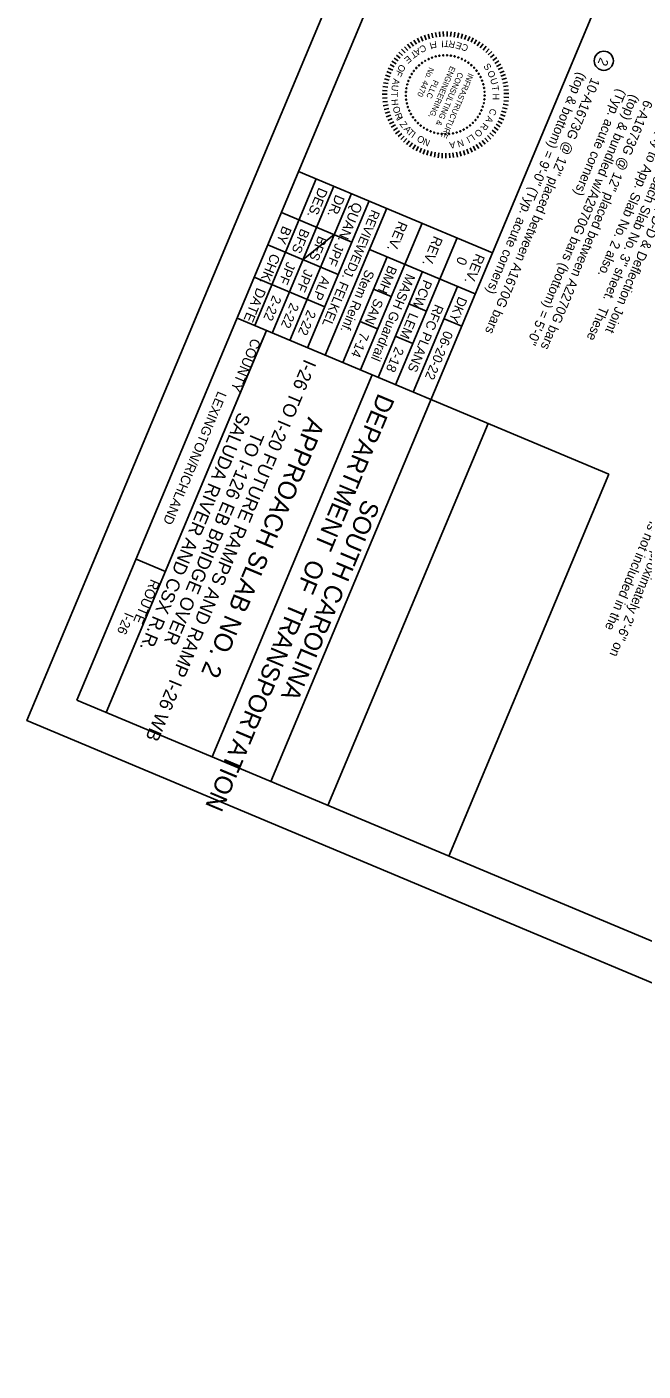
# Model space of a CAD drawing. Extents: x 1968564 to 1968701, y 796599 to 796766.
# Drawn here: x 1968563.8 to 1968596.1, y 796598.9 to 796669.3 of the extents above; entities that cross this region are included whole.
import ezdxf

# ---------------------------------------------------------------- set-up
doc = ezdxf.new("R2010")
doc.units = 0
for name, color, linetype in [('BR_AUTO DIMENSION', 7, 'Continuous'), ('BR_BORDER LINES', 7, 'Continuous'), ('BR_TEXT', 7, 'Continuous'), ('Level 31', 7, 'Continuous')]:
    doc.layers.add(name, color=color, linetype=linetype)

msp = doc.modelspace()

# ---------------------------------------------------------------- linework, layer by layer
at = {"layer": 'BR_AUTO DIMENSION'}
msp.add_circle((1968594.037, 796667.481), 0.502, dxfattribs=at)
at = {"layer": 'BR_BORDER LINES'}
for p, q in [((1968618.549, 796758.212), (1968566.464, 796634.028)), ((1968596.513, 796677.23), (1968588.212, 796657.44)), ((1968578.99, 796661.308), (1968575.767, 796653.623)), ((1968578.068, 796661.695), (1968588.212, 796657.44)), ((1968579.912, 796660.921), (1968576.689, 796653.236)), ((1968580.835, 796660.534), (1968577.611, 796652.849)), ((1968581.757, 796660.147), (1968578.534, 796652.462)), ((1968582.679, 796659.761), (1968579.456, 796652.076)), ((1968580.854, 796657.996), (1968577.166, 796659.543)), ((1968584.524, 796658.987), (1968581.3, 796651.302)), ((1968580.145, 796656.305), (1968576.456, 796657.852)), ((1968587.31, 796655.288), (1968581.777, 796657.609)), ((1968586.368, 796658.213), (1968583.145, 796650.528)), ((1968588.212, 796657.44), (1968576.609, 796629.774)), ((1968582.699, 796657.222), (1968580.378, 796651.689)), ((1968579.436, 796654.614), (1968575.747, 796656.161)), ((1968584.543, 796656.448), (1968582.222, 796650.915)), ((1968581.99, 796655.531), (1968582.912, 796655.145)), ((1968586.388, 796655.675), (1968584.067, 796650.142)), ((1968583.834, 796654.758), (1968584.756, 796654.371)), ((1968576.382, 796653.365), (1968568.001, 796633.384)), ((1968574.845, 796654.01), (1968594.308, 796645.846)), ((1968581.281, 796653.841), (1968582.203, 796653.454)), ((1968585.679, 796653.984), (1968586.601, 796653.597)), ((1968576.231, 796653.005), (1968568.001, 796633.384)), ((1968583.125, 796653.067), (1968584.047, 796652.68)), ((1968581.915, 796651.044), (1968573.534, 796631.062)), ((1968581.915, 796651.044), (1968581.915, 796651.044)), ((1968587.983, 796648.498), (1968579.603, 796628.518)), ((1968594.308, 796645.846), (1968585.928, 796625.865)), ((1968569.559, 796641.406), (1968571.096, 796640.761)), ((1968566.464, 796634.028), (1968643.927, 796601.539))]:
    msp.add_line(p, q, dxfattribs=at)
at = {"layer": 'BR_TEXT'}
for p, q in [((1968584.652, 796668.818), (1968584.737, 796668.578)), ((1968584.844, 796668.88), (1968584.915, 796668.635)), ((1968585.04, 796668.93), (1968585.095, 796668.681)), ((1968585.238, 796668.967), (1968585.278, 796668.716)), ((1968585.438, 796668.993), (1968585.463, 796668.74)), ((1968585.64, 796669.006), (1968585.649, 796668.752)), ((1968585.842, 796669.007), (1968585.836, 796668.753)), ((1968586.043, 796668.996), (1968586.022, 796668.742)), ((1968586.244, 796668.973), (1968586.207, 796668.721)), ((1968586.443, 796668.937), (1968586.39, 796668.688)), ((1968586.639, 796668.889), (1968586.571, 796668.643)), ((1968586.832, 796668.829), (1968586.749, 796668.588)), ((1968583.608, 796668.216), (1968583.774, 796668.022)), ((1968583.766, 796668.342), (1968583.919, 796668.139)), ((1968583.93, 796668.458), (1968584.071, 796668.246)), ((1968584.102, 796668.565), (1968584.23, 796668.344)), ((1968584.28, 796668.66), (1968584.394, 796668.433)), ((1968584.463, 796668.745), (1968584.563, 796668.511)), ((1968587.021, 796668.758), (1968586.924, 796668.523)), ((1968587.205, 796668.675), (1968587.094, 796668.446)), ((1968587.384, 796668.582), (1968587.259, 796668.36)), ((1968587.557, 796668.477), (1968587.418, 796668.263)), ((1968587.723, 796668.362), (1968587.572, 796668.157)), ((1968587.881, 796668.238), (1968587.718, 796668.042)), ((1968588.032, 796668.103), (1968587.858, 796667.918)), ((1968582.951, 796667.454), (1968583.167, 796667.319)), ((1968583.063, 796667.622), (1968583.271, 796667.474)), ((1968583.186, 796667.782), (1968583.384, 796667.622)), ((1968583.318, 796667.935), (1968583.506, 796667.763)), ((1968583.459, 796668.08), (1968583.636, 796667.897)), ((1968588.175, 796667.96), (1968587.989, 796667.786)), ((1968588.308, 796667.809), (1968588.112, 796667.646)), ((1968588.432, 796667.649), (1968588.227, 796667.499)), ((1968588.546, 796667.483), (1968588.332, 796667.345)), ((1968582.61, 796666.724), (1968582.852, 796666.645)), ((1968582.678, 796666.914), (1968582.915, 796666.82)), ((1968582.758, 796667.099), (1968582.989, 796666.992)), ((1968582.849, 796667.279), (1968583.073, 796667.158)), ((1968588.65, 796667.309), (1968588.428, 796667.185)), ((1968588.743, 796667.13), (1968588.513, 796667.02)), ((1968588.825, 796666.945), (1968588.589, 796666.849)), ((1968588.895, 796666.756), (1968588.654, 796666.674)), ((1968582.476, 796666.134), (1968582.728, 796666.1)), ((1968582.509, 796666.333), (1968582.759, 796666.284)), ((1968582.553, 796666.53), (1968582.8, 796666.466)), ((1968588.954, 796666.563), (1968588.708, 796666.496)), ((1968589, 796666.366), (1968588.751, 796666.315)), ((1968589.035, 796666.167), (1968588.783, 796666.131)), ((1968582.447, 796665.731), (1968582.702, 796665.729)), ((1968582.451, 796665.529), (1968582.706, 796665.542)), ((1968582.455, 796665.933), (1968582.709, 796665.915)), ((1968582.468, 796665.328), (1968582.721, 796665.357)), ((1968589.052, 796665.362), (1968588.798, 796665.387)), ((1968589.058, 796665.967), (1968588.804, 796665.946)), ((1968589.066, 796665.563), (1968588.811, 796665.573)), ((1968589.068, 796665.765), (1968588.813, 796665.76)), ((1968582.496, 796665.128), (1968582.747, 796665.172)), ((1968582.537, 796664.93), (1968582.785, 796664.99)), ((1968582.59, 796664.735), (1968582.834, 796664.81)), ((1968582.654, 796664.544), (1968582.893, 796664.633)), ((1968588.873, 796664.576), (1968588.633, 796664.662)), ((1968588.935, 796664.768), (1968588.691, 796664.839)), ((1968588.986, 796664.963), (1968588.738, 796665.02)), ((1968589.025, 796665.162), (1968588.774, 796665.203)), ((1968582.731, 796664.357), (1968582.963, 796664.46)), ((1968582.818, 796664.175), (1968583.044, 796664.292)), ((1968582.916, 796663.998), (1968583.135, 796664.129)), ((1968583.025, 796663.828), (1968583.235, 796663.972)), ((1968588.51, 796663.857), (1968588.298, 796663.998)), ((1968588.617, 796664.028), (1968588.397, 796664.156)), ((1968588.713, 796664.205), (1968588.486, 796664.32)), ((1968588.799, 796664.388), (1968588.565, 796664.489)), ((1968583.144, 796663.665), (1968583.345, 796663.822)), ((1968583.273, 796663.51), (1968583.464, 796663.678)), ((1968583.411, 796663.362), (1968583.591, 796663.542)), ((1968583.558, 796663.224), (1968583.727, 796663.414)), ((1968583.713, 796663.094), (1968583.87, 796663.295)), ((1968583.875, 796662.974), (1968584.02, 796663.184)), ((1968587.668, 796662.994), (1968587.521, 796663.202)), ((1968587.83, 796663.115), (1968587.67, 796663.314)), ((1968587.983, 796663.246), (1968587.812, 796663.435)), ((1968588.129, 796663.387), (1968587.946, 796663.564)), ((1968588.265, 796663.535), (1968588.072, 796663.702)), ((1968588.392, 796663.692), (1968588.189, 796663.846)), ((1968584.045, 796662.864), (1968584.176, 796663.083)), ((1968584.221, 796662.765), (1968584.339, 796662.991)), ((1968584.402, 796662.677), (1968584.506, 796662.91)), ((1968584.589, 796662.6), (1968584.678, 796662.838)), ((1968584.78, 796662.535), (1968584.855, 796662.778)), ((1968584.974, 796662.481), (1968585.034, 796662.728)), ((1968585.172, 796662.439), (1968585.217, 796662.69)), ((1968585.372, 796662.409), (1968585.401, 796662.662)), ((1968585.573, 796662.392), (1968585.587, 796662.646)), ((1968585.775, 796662.387), (1968585.773, 796662.641)), ((1968585.977, 796662.394), (1968585.96, 796662.648)), ((1968586.178, 796662.414), (1968586.145, 796662.666)), ((1968586.377, 796662.445), (1968586.329, 796662.695)), ((1968586.574, 796662.489), (1968586.511, 796662.736)), ((1968586.768, 796662.545), (1968586.69, 796662.787)), ((1968586.959, 796662.612), (1968586.866, 796662.849)), ((1968587.145, 796662.691), (1968587.038, 796662.922)), ((1968587.325, 796662.781), (1968587.204, 796663.005)), ((1968587.5, 796662.882), (1968587.366, 796663.099))]:
    msp.add_line(p, q, dxfattribs=at)
for centre, start, end in [((1968584.524, 796667.368), 36.3113, 216.3113), ((1968584.69, 796667.478), 30.77284, 210.77284), ((1968584.69, 796667.478), 210.77284, 30.77284), ((1968584.867, 796667.571), 25.23438, 205.23438), ((1968584.867, 796667.571), 205.23438, 25.23438), ((1968585.051, 796667.647), 19.69592, 199.69592), ((1968585.051, 796667.647), 199.69592, 19.69592), ((1968585.242, 796667.705), 14.15746, 194.15746), ((1968585.242, 796667.705), 194.15746, 14.15746), ((1968585.437, 796667.744), 8.619, 188.619), ((1968585.437, 796667.744), 188.619, 8.619), ((1968585.635, 796667.764), 3.08054, 183.08054), ((1968585.635, 796667.764), 183.08054, 3.08054), ((1968585.835, 796667.764), 357.54207, 177.54207), ((1968585.835, 796667.764), 177.54207, 357.54207), ((1968586.033, 796667.746), 172.00361, 352.00361), ((1968586.033, 796667.746), 352.00361, 172.00361), ((1968586.229, 796667.708), 166.46515, 346.46515), ((1968586.229, 796667.708), 346.46515, 166.46515), ((1968586.42, 796667.652), 160.92669, 340.92669), ((1968586.42, 796667.652), 340.92669, 160.92669), ((1968586.605, 796667.577), 155.38823, 335.38823), ((1968586.605, 796667.577), 335.38823, 155.38823), ((1968586.782, 796667.485), 149.84977, 329.84977), ((1968586.782, 796667.485), 329.84977, 149.84977), ((1968586.949, 796667.377), 144.3113, 324.3113), ((1968586.949, 796667.377), 324.3113, 144.3113), ((1968583.986, 796666.786), 58.46515, 238.46515), ((1968583.986, 796666.786), 238.46515, 58.46515), ((1968584.099, 796666.95), 52.92669, 232.92669), ((1968584.099, 796666.95), 232.92669, 52.92669), ((1968584.227, 796667.103), 47.38823, 227.38823), ((1968584.227, 796667.103), 227.38823, 47.38823), ((1968584.369, 796667.243), 41.84977, 221.84977), ((1968584.369, 796667.243), 221.84977, 41.84977), ((1968584.524, 796667.368), 216.3113, 36.3113), ((1968587.105, 796667.252), 138.77284, 318.77284), ((1968587.105, 796667.252), 318.77284, 138.77284), ((1968587.248, 796667.114), 133.23438, 313.23438), ((1968587.248, 796667.114), 313.23438, 133.23438), ((1968587.377, 796666.962), 127.69592, 307.69592), ((1968587.377, 796666.962), 307.69592, 127.69592), ((1968587.491, 796666.798), 122.15746, 302.15746), ((1968587.491, 796666.798), 302.15746, 122.15746), ((1968583.708, 796666.044), 80.619, 260.619), ((1968583.708, 796666.044), 260.619, 80.619), ((1968583.75, 796666.239), 75.08054, 255.08054), ((1968583.75, 796666.239), 255.08054, 75.08054), ((1968583.811, 796666.428), 69.54207, 249.54207), ((1968583.811, 796666.428), 249.54207, 69.54207), ((1968583.89, 796666.611), 64.00361, 244.00361), ((1968583.89, 796666.611), 244.00361, 64.00361), ((1968587.588, 796666.624), 116.619, 296.619), ((1968587.588, 796666.624), 296.619, 116.619), ((1968587.668, 796666.442), 111.08054, 291.08054), ((1968587.668, 796666.442), 291.08054, 111.08054), ((1968587.731, 796666.252), 105.54207, 285.54207), ((1968587.731, 796666.252), 285.54207, 105.54207), ((1968587.774, 796666.058), 100.00361, 280.00361), ((1968587.774, 796666.058), 280.00361, 100.00361), ((1968583.68, 796665.647), 91.69592, 271.69592), ((1968583.684, 796665.846), 86.15746, 266.15746), ((1968583.695, 796665.448), 97.23438, 277.23438), ((1968583.68, 796665.647), 271.69592, 91.69592), ((1968583.684, 796665.846), 266.15746, 86.15746), ((1968583.695, 796665.448), 277.23438, 97.23438), ((1968587.758, 796665.265), 77.84977, 257.84977), ((1968587.758, 796665.265), 257.84977, 77.84977), ((1968587.791, 796665.462), 83.38823, 263.38823), ((1968587.799, 796665.86), 94.46515, 274.46515), ((1968587.805, 796665.661), 88.92669, 268.92669), ((1968587.791, 796665.462), 263.38823, 83.38823), ((1968587.799, 796665.86), 274.46515, 94.46515), ((1968587.805, 796665.661), 268.92669, 88.92669), ((1968583.73, 796665.251), 102.77284, 282.77284), ((1968583.73, 796665.251), 282.77284, 102.77284), ((1968583.783, 796665.059), 108.3113, 288.3113), ((1968583.783, 796665.059), 288.3113, 108.3113), ((1968583.854, 796664.873), 113.84977, 293.84977), ((1968583.854, 796664.873), 293.84977, 113.84977), ((1968583.943, 796664.695), 119.38823, 299.38823), ((1968583.943, 796664.695), 299.38823, 119.38823), ((1968587.549, 796664.707), 61.23438, 241.23438), ((1968587.549, 796664.707), 241.23438, 61.23438), ((1968587.636, 796664.886), 66.77284, 246.77284), ((1968587.636, 796664.886), 246.77284, 66.77284), ((1968587.706, 796665.073), 72.3113, 252.3113), ((1968587.706, 796665.073), 252.3113, 72.3113), ((1968584.049, 796664.526), 124.92669, 304.92669), ((1968584.049, 796664.526), 304.92669, 124.92669), ((1968584.17, 796664.368), 130.46515, 310.46515), ((1968584.17, 796664.368), 310.46515, 130.46515), ((1968584.306, 796664.222), 136.00361, 316.00361), ((1968584.306, 796664.222), 316.00361, 136.00361), ((1968584.456, 796664.091), 141.54207, 321.54207), ((1968584.456, 796664.091), 321.54207, 141.54207), ((1968584.618, 796663.974), 147.08054, 327.08054), ((1968584.618, 796663.974), 327.08054, 147.08054), ((1968584.79, 796663.874), 152.619, 332.619), ((1968584.79, 796663.874), 332.619, 152.619), ((1968586.707, 796663.88), 28.00361, 208.00361), ((1968586.707, 796663.88), 208.00361, 28.00361), ((1968586.879, 796663.982), 33.54207, 213.54207), ((1968586.879, 796663.982), 213.54207, 33.54207), ((1968587.04, 796664.1), 39.08054, 219.08054), ((1968587.04, 796664.1), 219.08054, 39.08054), ((1968587.188, 796664.232), 44.619, 224.619), ((1968587.188, 796664.232), 224.619, 44.619), ((1968587.323, 796664.379), 50.15746, 230.15746), ((1968587.323, 796664.379), 230.15746, 50.15746), ((1968587.444, 796664.538), 55.69592, 235.69592), ((1968587.444, 796664.538), 235.69592, 55.69592), ((1968584.971, 796663.79), 158.15746, 338.15746), ((1968584.971, 796663.79), 338.15746, 158.15746), ((1968585.159, 796663.725), 163.69592, 343.69592), ((1968585.159, 796663.725), 343.69592, 163.69592), ((1968585.353, 796663.678), 349.23438, 169.23438), ((1968585.353, 796663.678), 169.23438, 349.23438), ((1968585.55, 796663.65), 354.77284, 174.77284), ((1968585.55, 796663.65), 174.77284, 354.77284), ((1968585.749, 796663.641), 0.3113, 180.3113), ((1968585.749, 796663.641), 180.3113, 0.3113), ((1968585.948, 796663.651), 5.84977, 185.84977), ((1968585.948, 796663.651), 185.84977, 5.84977), ((1968586.146, 796663.681), 11.38823, 191.38823), ((1968586.146, 796663.681), 191.38823, 11.38823), ((1968586.339, 796663.729), 16.92669, 196.92669), ((1968586.339, 796663.729), 196.92669, 16.92669), ((1968586.527, 796663.796), 22.46515, 202.46515), ((1968586.527, 796663.796), 202.46515, 22.46515)]:
    msp.add_arc(centre, 0.028, start, end, dxfattribs=at)
at = {"layer": 'Level 31'}
for p, q in [((1968579.932, 796658.382), (1968578.301, 796657.078)), ((1968576.101, 796641.734), (1968576.101, 796641.734))]:
    msp.add_line(p, q, dxfattribs=at)
msp.add_lwpolyline([(1968619.541, 796765.748), (1968563.846, 796632.955), (1968644.997, 796598.919), (1968700.693, 796731.712)], close=True, dxfattribs=at)

# ---------------------------------------------------------------- texts
at = {"layer": 'BR_AUTO DIMENSION'}
msp.add_text('2', height=0.5, rotation=247.24601, dxfattribs=at).set_placement((1968593.851, 796667.685))
at = {"layer": 'BR_TEXT'}
for s, height, rotation, p in [('A', 0.349, 207.77284, (1968584.337, 796668.169)), ('C', 0.349, 201.77284, (1968584.66, 796668.334)), ('I', 0.349, 195.77284, (1968585.01, 796668.444)), ('F', 0.349, 187.01728, (1968585.274, 796668.516)), ('I', 0.349, 181.01728, (1968585.655, 796668.535)), ('T', 0.349, 172.27105, (1968585.971, 796668.531)), ('R', 0.349, 166.27105, (1968586.289, 796668.474)), ('E', 0.349, 160.27105, (1968586.649, 796668.378)), ('C', 0.349, 154.27105, (1968586.993, 796668.253)), ('E', 0.349, 219.77284, (1968583.797, 796667.775)), ('T', 0.349, 213.77284, (1968584.111, 796668.028)), ('F', 0.349, 243.77284, (1968583.225, 796667.011)), ('O', 0.349, 237.77284, (1968583.4, 796667.334)), ('No. 4470', 0.2991, 246.77284, (1968584.901, 796667.163)), ('ENGINEERING,', 0.29909, 246.77284, (1968586.014, 796667.226)), ('CONSULTING &', 0.29909, 246.77284, (1968586.424, 796666.908)), ('INFRASTRUCTURE', 0.29909, 246.77284, (1968586.963, 796666.862)), ('S', 0.349, 306.15428, (1968587.718, 796667.189)), ('(top & bottom) = 9\'-0" (Typ. acute corners)', 0.49995, 247.24601, (1968592.703, 796666.919)), ('O', 0.349, 297.12425, (1968587.921, 796666.864)), ('U', 0.349, 263.77284, (1968582.954, 796666.24)), ('A', 0.349, 257.77284, (1968583.034, 796666.571)), ('PLLC', 0.2991, 246.77284, (1968585.131, 796666.504)), ('10-A1673G @ 12" placed between A1670G bars ', 0.49995, 247.24601, (1968593.394, 796666.629)), ('U', 0.349, 288.09423, (1968588.079, 796666.507)), ('T', 0.349, 279.0642, (1968588.173, 796666.15)), ('(Typ. acute corners)', 0.49995, 247.24601, (1968594.777, 796666.049)), ('Detail, see "Approach Slab No. 3" sheet.  These ', 0.49995, 247.24601, (1968598.628, 796666.08)), ('details apply to App. Slab No. 2 also.', 0.49995, 247.24601, (1968597.936, 796666.37)), ('T', 0.349, 269.77284, (1968582.902, 796665.864)), ('H', 0.349, 275.77284, (1968582.912, 796665.456)), ('H', 0.349, 270.03418, (1968588.217, 796665.763)), ('(top) & bundled w/A2970G bars (bottom) = 5\'-0"', 0.49995, 247.24601, (1968595.469, 796665.759)), ('6-A1673G @ 12" placed between A2270G bars ', 0.49995, 247.24601, (1968596.16, 796665.469)), ('For Sections A-A, B-B, D-D & Deflection Joint ', 0.49995, 247.24601, (1968599.32, 796665.79)), ('O', 0.349, 285.77284, (1968582.982, 796665.044)), ('R', 0.349, 291.77284, (1968583.085, 796664.669)), ('A', 0.349, 242.9441, (1968587.973, 796664.619)), ('C', 0.349, 251.97413, (1968588.117, 796665.012)), ('I', 0.349, 299.57989, (1968583.183, 796664.414)), ('Z', 0.349, 304.6414, (1968583.332, 796664.173)), ('A', 0.349, 310.6414, (1968583.546, 796663.893)), ('T', 0.349, 316.6414, (1968583.721, 796663.686)), ('O', 0.349, 224.88405, (1968587.488, 796663.947)), ('R', 0.349, 233.91408, (1968587.749, 796664.261)), ('I', 0.349, 325.15527, (1968583.93, 796663.487)), ('O', 0.349, 330.4545, (1968584.217, 796663.299)), ('N', 0.349, 336.4545, (1968584.537, 796663.117)), ('A', 0.349, 188.76396, (1968586.242, 796663.266)), ('N', 0.349, 197.79398, (1968586.647, 796663.379)), ('I', 0.349, 206.82401, (1968586.928, 796663.525)), ('L', 0.349, 214.35403, (1968587.149, 796663.66)), ('center and parallel to centerline of approach slab. Weight of bar supports is not included in the ', 0.49995, 247.24601, (1968604.852, 796663.47)), ('Space CHCU bolsters to provide adequate support for top reinforcing steel, approximately 2\'-6" on ', 0.49995, 247.24601, (1968605.544, 796663.18)), ('DES.', 0.52, 247.24601, (1968579.126, 796660.884)), ('DR.', 0.52, 247.24601, (1968580.018, 796660.514)), ('QUAN.', 0.52, 247.24601, (1968580.946, 796660.126)), ('REVIEWED', 0.48, 247.24601, (1968581.898, 796659.724)), ('REV.', 0.52, 247.24601, (1968583.306, 796659.13)), ('BY', 0.52, 247.24601, (1968577.243, 796658.88)), ('BFS', 0.5, 247.24601, (1968578.195, 796658.737)), ('BFS', 0.5, 247.24601, (1968579.114, 796658.352)), ('REV.', 0.52, 247.24601, (1968585.15, 796658.357)), ('JPF', 0.5, 247.24601, (1968580.003, 796657.969)), ('CHK.', 0.52, 247.24601, (1968576.643, 796657.436)), ('JPF', 0.5, 247.24601, (1968577.464, 796656.995)), ('0', 0.52, 247.24601, (1968586.443, 796657.277)), ('REV.', 0.52, 247.24601, (1968587.354, 796657.432)), ('JPF', 0.5, 247.24601, (1968578.383, 796656.61)), ('ALP', 0.5, 247.24601, (1968579.28, 796656.244)), ('J. FELKEL', 0.5, 247.24601, (1968580.518, 796656.631)), ('Stem Reinf.', 0.5, 247.24601, (1968581.587, 796656.594)), ('MASH Guardrail', 0.5, 247.24601, (1968583.725, 796656.382)), ('BMH', 0.5, 247.24601, (1968582.775, 796656.806)), ('DATE', 0.52, 247.24601, (1968575.893, 796655.646)), ('PCW', 0.5, 247.24601, (1968584.613, 796656.064)), ('2-22', 0.5, 247.24601, (1968576.728, 796655.239)), ('2-22', 0.5, 247.24601, (1968577.647, 796654.854)), ('SAN', 0.5, 247.24601, (1968582.052, 796655.081)), ('DKY', 0.5, 247.24601, (1968586.45, 796655.179)), ('2-22', 0.5, 247.24601, (1968578.54, 796654.479)), ('LEM', 0.5, 247.24601, (1968583.886, 796654.331)), ('RFC PLANS', 0.5, 247.24601, (1968585.21, 796654.781)), ('COUNTY', 0.52, 247.24601, (1968575.628, 796652.999)), ('7-14', 0.5, 247.24601, (1968581.312, 796653.317)), ('06-20-22', 0.5, 247.24601, (1968585.701, 796653.392)), ('2-18', 0.5, 247.24601, (1968583.139, 796652.55)), ('I-26 TO I-20 FUTURE RAMPS AND RAMP I-26 WB', 0.7, 247.24601, (1968578.367, 796651.91)), ('LEXINGTON/RICHLAND', 0.49998, 247.24601, (1968573.848, 796650.223)), ('DEPARTMENT  OF  TRANSPORTATION', 0.94348, 247.24601, (1968582.243, 796650.129)), ('SALUDA RIVER AND CSX R.R.', 0.7, 247.24601, (1968574.926, 796649.136)), ('APPROACH SLAB NO. 2', 0.96, 247.24601, (1968578.576, 796648.877)), ('TO I-126 EB BRIDGE OVER', 0.7, 247.24601, (1968575.638, 796648.118)), ('SOUTH CAROLINA', 0.94348, 247.24601, (1968581.47, 796644.586)), ('ROUTE', 0.52, 247.24601, (1968570.342, 796640.395)), ('I-26', 0.5, 247.24601, (1968568.996, 796638.655))]:
    msp.add_text(s, height=height, rotation=rotation, dxfattribs=at).set_placement(p)

doc.saveas('drawing.dxf')
